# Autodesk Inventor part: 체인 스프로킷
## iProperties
Created: 2014-11
Part Number: 체인 스프로킷
Material: Steel
Document SubType Name: Modeling
Designer: KYOUNG IL JANG
Density: 7.85 g/cm^3
Mass: 738.264 g
Surface Area: 236.923 cm^2
Volume: 94.0463 cm^3
CustomPartVersion: 1
Company: 한국ATC센터
Author: KYOUNG IL JANG
